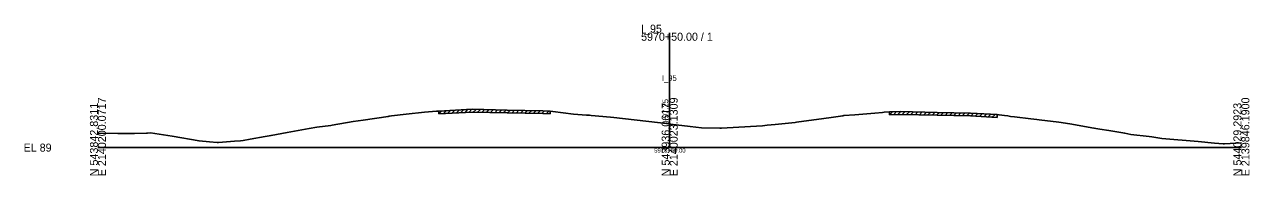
# Model space of a CAD drawing. Extents: x -12534 to 3403, y -1332 to 21983.
# Drawn here: x -25.7 to 402.8, y 5490.3 to 5542.9 of the extents above; entities that cross this region are included whole.
import ezdxf

# ---------------------------------------------------------------- set-up
doc = ezdxf.new("R2010")
doc.units = 0
for name, color, linetype in [('RD_GPK_XS_Cell', 7, 'Continuous'), ('RD_XS_ExGround', 7, 'Continuous'), ('RD_XS_ExPaveRet', 7, 'Continuous'), ('RD_XS_TX_Baseline', 7, 'Continuous'), ('RD_XS_TX_Elev_EX', 7, 'Continuous'), ('RD_XS_TX_Station', 7, 'Continuous')]:
    doc.layers.add(name, color=color, linetype=linetype)

msp = doc.modelspace()

# ---------------------------------------------------------------- linework, layer by layer
at = {"layer": 'RD_GPK_XS_Cell'}
for p, q in [((200, 5500), (200, 5540.05)), ((0, 5500), (200, 5500)), ((200, 5500), (400, 5500))]:
    msp.add_line(p, q, dxfattribs=at)
at = {"layer": 'RD_XS_ExGround'}
msp.add_lwpolyline([(0, 5505.01), (6.91, 5504.91), (12.8, 5504.97), (16.97, 5504.98), (17.38, 5505.02), (18.39, 5505.1), (25.95, 5503.95), (35.36, 5502.36), (38.99, 5501.96), (41.72, 5501.76), (42.14, 5501.79), (47.78, 5502.24), (49.91, 5502.37), (50.84, 5502.53), (53.26, 5502.95), (58.44, 5503.87), (60.55, 5504.26), (66.14, 5505.24), (71.38, 5506.2), (73.93, 5506.67), (76.61, 5507.07), (81.43, 5507.76), (81.93, 5507.83), (89.26, 5509.06), (92.74, 5509.62), (101.49, 5510.9), (101.89, 5510.96), (102.67, 5511.05), (107.87, 5511.65), (114.28, 5512.36), (118.45, 5512.7), (119.29, 5512.74), (130.86, 5513.35), (143.2, 5513.08), (155.69, 5512.86), (158.23, 5512.73), (159.14, 5512.63), (166.36, 5511.66), (167.88, 5511.51), (170.95, 5511.32), (171.98, 5511.29), (172.51, 5511.23), (179.29, 5510.58), (180.44, 5510.48), (195.7, 5508.75), (200, 5508.25), (200.32, 5508.21), (207.21, 5507.37), (211.15, 5506.92), (217.59, 5506.72), (218.11, 5506.76), (228.26, 5507.32), (232.46, 5507.61), (234.11, 5507.88), (236.91, 5508.06), (243.9, 5508.76), (244.42, 5508.82), (253.88, 5510.19), (256.46, 5510.54), (260.58, 5511.11), (260.98, 5511.14), (264.8, 5511.41), (271.73, 5512.01), (274.4, 5512.26), (275.06, 5512.3), (276.87, 5512.46), (280.62, 5512.6), (293.63, 5512.29), (305.2, 5512.02), (314.53, 5511.5), (315.24, 5511.38), (317.1, 5511.17), (318.27, 5511.02), (319.21, 5510.9), (320.59, 5510.74), (326.34, 5510.04), (328.45, 5509.78), (329.27, 5509.68), (336.09, 5508.84), (339.99, 5508.24), (348.41, 5506.82), (350.45, 5506.47), (353.65, 5505.94), (359.18, 5504.98), (361.38, 5504.62), (367.75, 5503.86), (368.63, 5503.73), (372.17, 5503.22), (384.91, 5502.16), (390.64, 5501.52), (393.58, 5501.33), (394.08, 5501.37), (400, 5501.68)], dxfattribs=at)
at = {"layer": 'RD_XS_ExPaveRet'}
for p, q in [((119.29, 5511.74), (120.34, 5512.79)), ((119.29, 5511.74), (119.29, 5512.74)), ((119.29, 5511.74), (130.86, 5512.35)), ((120.79, 5511.82), (121.84, 5512.87)), ((122.29, 5511.89), (123.34, 5512.95)), ((123.79, 5511.97), (124.84, 5513.03)), ((125.29, 5512.05), (126.34, 5513.11)), ((126.79, 5512.13), (127.84, 5513.19)), ((128.29, 5512.21), (129.34, 5513.27)), ((129.79, 5512.29), (130.84, 5513.35)), ((130.86, 5512.35), (143.2, 5512.08)), ((131.29, 5512.34), (132.27, 5513.32)), ((132.79, 5512.31), (133.77, 5513.28)), ((134.29, 5512.27), (135.27, 5513.25)), ((135.79, 5512.24), (136.77, 5513.22)), ((137.29, 5512.21), (138.27, 5513.19)), ((138.79, 5512.17), (139.77, 5513.15)), ((140.29, 5512.14), (141.27, 5513.12)), ((141.79, 5512.11), (142.77, 5513.09)), ((143.2, 5512.08), (155.69, 5511.86)), ((143.29, 5512.07), (144.27, 5513.06)), ((144.79, 5512.05), (145.77, 5513.03)), ((146.29, 5512.02), (147.27, 5513.01)), ((147.79, 5512), (148.77, 5512.98)), ((149.29, 5511.97), (150.27, 5512.95)), ((150.79, 5511.95), (151.77, 5512.93)), ((152.29, 5511.92), (153.27, 5512.9)), ((153.79, 5511.89), (154.77, 5512.88)), ((155.29, 5511.87), (156.25, 5512.83)), ((155.69, 5511.86), (158.23, 5511.73)), ((156.79, 5511.8), (157.74, 5512.75)), ((158.23, 5512.73), (158.23, 5511.73)), ((276.87, 5511.46), (277.91, 5512.5)), ((276.87, 5511.46), (276.87, 5512.46)), ((276.87, 5511.46), (280.62, 5511.6)), ((278.37, 5511.52), (279.41, 5512.56)), ((279.87, 5511.57), (280.89, 5512.6)), ((280.62, 5511.6), (293.63, 5511.29)), ((281.37, 5511.59), (282.35, 5512.56)), ((282.87, 5511.55), (283.85, 5512.53)), ((284.37, 5511.51), (285.35, 5512.49)), ((285.87, 5511.48), (286.85, 5512.46)), ((287.37, 5511.44), (288.35, 5512.42)), ((288.87, 5511.41), (289.85, 5512.38)), ((290.37, 5511.37), (291.35, 5512.35)), ((291.87, 5511.34), (292.85, 5512.31)), ((293.37, 5511.3), (294.35, 5512.28)), ((293.63, 5511.29), (305.2, 5511.02)), ((294.87, 5511.27), (295.85, 5512.24)), ((296.37, 5511.23), (297.35, 5512.21)), ((297.87, 5511.2), (298.85, 5512.17)), ((299.37, 5511.16), (300.35, 5512.14)), ((300.87, 5511.13), (301.85, 5512.1)), ((302.37, 5511.09), (303.35, 5512.07)), ((303.87, 5511.06), (304.85, 5512.03)), ((305.2, 5511.02), (314.53, 5510.5)), ((305.37, 5511.01), (306.32, 5511.96)), ((306.87, 5510.93), (307.82, 5511.88)), ((308.37, 5510.85), (309.32, 5511.79)), ((309.87, 5510.76), (310.82, 5511.71)), ((311.37, 5510.68), (312.32, 5511.62)), ((312.87, 5510.59), (313.82, 5511.54)), ((314.53, 5511.5), (314.53, 5510.5))]:
    msp.add_line(p, q, dxfattribs=at)

# ---------------------------------------------------------------- texts
at = {"layer": 'RD_GPK_XS_Cell'}
for s, p in [('I_95', (190, 5540.05)), ('5970+50.00 / 1', (190, 5537.25)), ('EL 89', (-26, 5498.6))]:
    msp.add_text(s, height=2.8, dxfattribs=at).set_placement(p)
for s, p in [('N 543842.8311', (0, 5490)), ('E 2140200.0717', (2.8, 5490)), ('N 543936.0617', (200, 5490)), ('E 2140023.1309', (202.8, 5490)), ('N 544029.2923', (400, 5490)), ('E 2139846.1900', (402.8, 5490))]:
    msp.add_text(s, height=2.8, rotation=90, dxfattribs=at).set_placement(p)
at = {"layer": 'RD_XS_TX_Baseline'}
msp.add_text('I_95', height=2, dxfattribs=at).set_placement((197.28, 5523.25))
at = {"layer": 'RD_XS_TX_Elev_EX'}
msp.add_text('97.25', height=2, rotation=90, dxfattribs=at).set_placement((199.5, 5510.25))
at = {"layer": 'RD_XS_TX_Station'}
msp.add_text('5970+50.00', height=1.5, dxfattribs=at).set_placement((194.57, 5498.25))

doc.saveas('drawing.dxf')
